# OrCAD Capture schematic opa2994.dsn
size A; title: OPA2994 Reference Design; rev: A; note: N/A
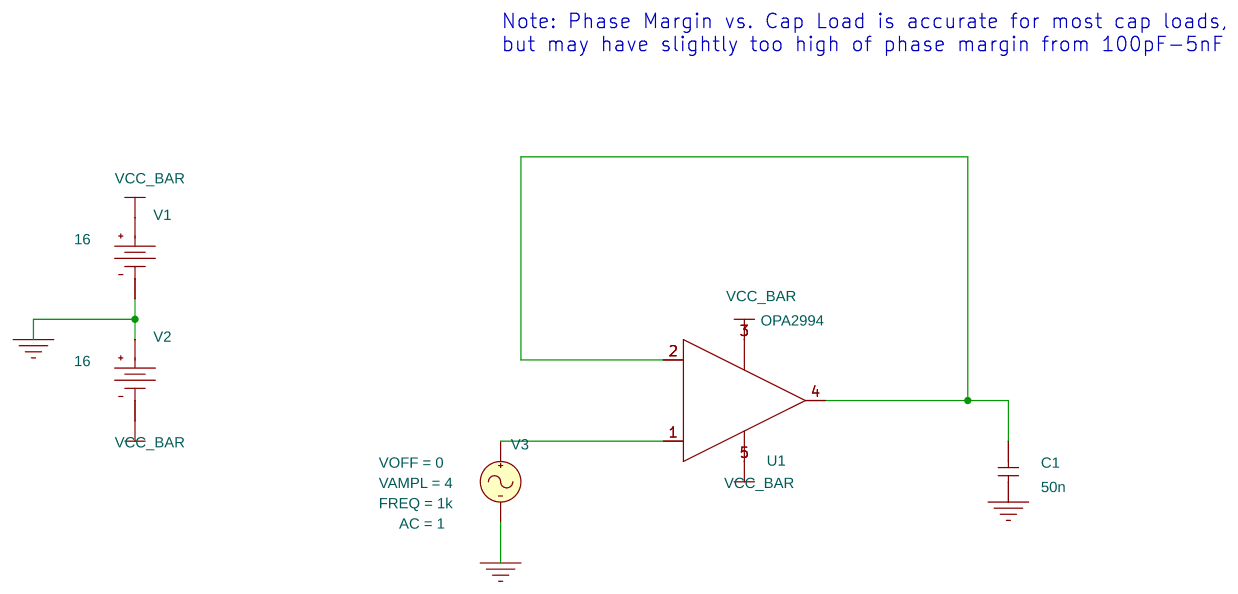
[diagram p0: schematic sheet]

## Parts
C1  50n  [cap196]
U1  OPA2994
V1  VDC
V2  VDC
V3  VSIN

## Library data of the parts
C1 = C
U1 = OPA2994
V1 V2 = VDC: DC: 16
V3 = VSIN: AC: 1; FREQ: 1k; VAMPL: 4; VOFF: 0

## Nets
VCC: U1.5(V+) V1.0(+)
VEE: U1.3(V-) V2.1(-)
0: C1.1 V1.1(-) V2.0(+) V3.2(-)
N00405: U1.1(+) V3.1(+)
N00409: C1.2 U1.2(-) U1.4(OUT)

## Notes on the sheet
- Note: Phase Margin vs. Cap Load is accurate for most cap loads,
  but may have slightly too high of phase margin from 100pF-5nF
